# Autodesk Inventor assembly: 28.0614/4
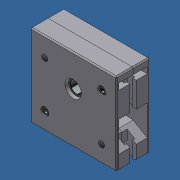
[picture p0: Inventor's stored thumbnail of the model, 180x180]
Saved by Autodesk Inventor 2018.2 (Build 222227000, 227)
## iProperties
Created: 2018-05
Part Number: 28.0614/4
Document SubType Name: Assembly
Designer: amoles
Description: TIMING BELT PULLEY T45 16mm
Stock Number: 28.0614 TIMING BELT PULLEY T45
Author: amoles
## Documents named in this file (12)
- Y:\INVENTOR LIBRARIES\PARTS LIBRARY\READY FOR USE MODULES LR\28.0614_4 TIMING BELT PULLEY T45 16mm.iam
- Y:\INVENTOR LIBRARIES\PARTS LIBRARY\READY FOR USE MODULES LR\SUBCOMPONENTS\28.0614 TIMING BELT PULLEY T45 RIGHT PLATE.ipt
- Y:\INVENTOR LIBRARIES\PARTS LIBRARY\READY FOR USE MODULES LR\SUBCOMPONENTS\SHIM DIN 988 - 25 x 35 x 0,1.ipt
- 00005263.ipt
- Y:\INVENTOR LIBRARIES\PARTS LIBRARY\READY FOR USE MODULES LR\Subcomponents\28.0083 BEARING.ipt
- Y:\INVENTOR LIBRARIES\PARTS LIBRARY\READY FOR USE MODULES LR\SUBCOMPONENTS\SHIM DIN 988 - 37 x 47 x 0,1.ipt
- 00005262.ipt
- Y:\INVENTOR LIBRARIES\PARTS LIBRARY\READY FOR USE MODULES LR\SUBCOMPONENTS\28.0614 TIMING BELT PULLEY T45 LEFT PLATE.ipt
- Y:\INVENTOR LIBRARIES\PARTS LIBRARY\FASTENING ELEMENTS\SCREWS CAP\M6X30 HIGH HEAD.ipt
- 00005264.ipt
- Y:\INVENTOR LIBRARIES\PARTS LIBRARY\END CAPS\22.1203 HOLE CAP M6.ipt
- Y:\INVENTOR LIBRARIES\PARTS LIBRARY\READY FOR USE MODULES LR\SUBCOMPONENTS\28.0047_3 T45 PULLEY 16mm.ipt
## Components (17 placed, 8 different names)
1. 28.0614 TIMING BELT PULLEY T45 RIGHT PLATE:1 — Flush:1, Flush:2, Flush:3, Mate:5, Mate:6, Mate:7, Angle:1, Insert:7, Insert:8, Insert:11, Insert:12, Angle:2
2. 28.0047_3 T45 PULLEY 16mm:1 — Insert:1, Insert:2, Mate:1, Mate:3, Mate:5, Mate:6, Mate:8, Angle:2
3. 00005263:1 — Insert:1, Insert:3
4. 00005263:2 — Insert:2, Insert:4
5. 28.0083 BEARING:1 — Insert:4, Mate:4
6. 28.0083 BEARING:2 — Insert:3, Mate:2
7. 00005262:1 — Mate:1, Mate:2
8. 00005262:2 — Mate:3, Mate:4
9. 28.0614 TIMING BELT PULLEY T45 LEFT PLATE:1 — Mate:7, Mate:8, Angle:1, Insert:5, Insert:6, Insert:9, Insert:10
10. 00005264:1 — Insert:6
11. 00005264:2 — Insert:5
12. 00005264:3 — Insert:8
13. 00005264:4 — Insert:7
14. 22.1203 HOLE CAP M6:1 — Insert:9
15. 22.1203 HOLE CAP M6:2 — Insert:10
16. 22.1203 HOLE CAP M6:3 — Insert:12
17. 22.1203 HOLE CAP M6:4 — Insert:11
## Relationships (25: Insert 12, Mate 8, Flush 3, Angle 2)
- Flush:1: 28.0614 TIMING BELT PULLEY T45 RIGHT PLATE:1
- Flush:2: 28.0614 TIMING BELT PULLEY T45 RIGHT PLATE:1
- Flush:3: 28.0614 TIMING BELT PULLEY T45 RIGHT PLATE:1
- Insert:1: 28.0047_3 T45 PULLEY 16mm:1 ↔ 00005263:1
- Insert:2: 28.0047_3 T45 PULLEY 16mm:1 ↔ 00005263:2
- Insert:3: 00005263:1 ↔ 28.0083 BEARING:2
- Insert:4: 00005263:2 ↔ 28.0083 BEARING:1
- Mate:1: 28.0047_3 T45 PULLEY 16mm:1 ↔ 00005262:1
- Mate:2: 28.0083 BEARING:2 ↔ 00005262:1
- Mate:3: 28.0047_3 T45 PULLEY 16mm:1 ↔ 00005262:2
- Mate:4: 28.0083 BEARING:1 ↔ 00005262:2
- Mate:5: 28.0614 TIMING BELT PULLEY T45 RIGHT PLATE:1 ↔ 28.0047_3 T45 PULLEY 16mm:1
- Mate:6: 28.0614 TIMING BELT PULLEY T45 RIGHT PLATE:1 ↔ 28.0047_3 T45 PULLEY 16mm:1
- Mate:7: 28.0614 TIMING BELT PULLEY T45 RIGHT PLATE:1 ↔ 28.0614 TIMING BELT PULLEY T45 LEFT PLATE:1
- Mate:8: 28.0047_3 T45 PULLEY 16mm:1 ↔ 28.0614 TIMING BELT PULLEY T45 LEFT PLATE:1
- Angle:1: 28.0614 TIMING BELT PULLEY T45 RIGHT PLATE:1 ↔ 28.0614 TIMING BELT PULLEY T45 LEFT PLATE:1
- Insert:5: 28.0614 TIMING BELT PULLEY T45 LEFT PLATE:1 ↔ 00005264:2
- Insert:6: 28.0614 TIMING BELT PULLEY T45 LEFT PLATE:1 ↔ 00005264:1
- Insert:7: 28.0614 TIMING BELT PULLEY T45 RIGHT PLATE:1 ↔ 00005264:4
- Insert:8: 28.0614 TIMING BELT PULLEY T45 RIGHT PLATE:1 ↔ 00005264:3
- Insert:9: 28.0614 TIMING BELT PULLEY T45 LEFT PLATE:1 ↔ 22.1203 HOLE CAP M6:1
- Insert:10: 28.0614 TIMING BELT PULLEY T45 LEFT PLATE:1 ↔ 22.1203 HOLE CAP M6:2
- Insert:11: 28.0614 TIMING BELT PULLEY T45 RIGHT PLATE:1 ↔ 22.1203 HOLE CAP M6:4
- Insert:12: 28.0614 TIMING BELT PULLEY T45 RIGHT PLATE:1 ↔ 22.1203 HOLE CAP M6:3
- Angle:2: 28.0614 TIMING BELT PULLEY T45 RIGHT PLATE:1 ↔ 28.0047_3 T45 PULLEY 16mm:1
